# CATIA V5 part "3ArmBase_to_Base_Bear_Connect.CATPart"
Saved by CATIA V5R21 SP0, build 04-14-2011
Part number: ArmBase_to_Base_Bear_Connect
Bounding box of the stored display mesh (mm): x 0 to 8, y -32 to 32, z -25.5 to 25.5
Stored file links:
  K:\Arm_Detailed_Design_Assembly_Manu\3ArmBase_to_Base_Bear_Connect.CATPart
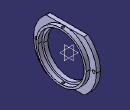
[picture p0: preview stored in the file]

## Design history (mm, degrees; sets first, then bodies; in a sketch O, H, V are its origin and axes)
Body1 (main body)
  Sketch1 on yz-plane, origin (0, 0, 0), H (0, 1, 0), V (0, 0, 1)
    circle A1 centre (0, 0) radius 32
    circle A2 centre (0, 0) radius 21.5
    radius A2 = 21.5
    radius A1 = 32
  Pad1: profile Sketch1, direction (1, 0, 0), length 4
  Sketch2 on end face of Pad1, origin (4, 0, 0), H (0, 1, 0), V (0, 0, 1)
    circle A1 centre (0, 0) radius 23.5
    circle A2 centre (0, 0) radius 25.5
    radius A2 = 25.5
    radius A1 = 23.5
  Pad2: profile Sketch2, direction (1, 0, 0), length 4
  Sketch3 on start face of Pad1, origin (0, 0, 0), H (0, -1, 0), V (0, 0, 1)
    circle A1 centre (29, 0) radius 1.5
    point P1 (29, 0)
    point P2 (30.5, 0)
    circle A2 centre (-29, 0) radius 1.5
    point P3 (-29, 0)
    line L1 (-30.0408, 34.0267) -> (31.4698, 34.0267)
    line L2 (31.4698, 34.0267) -> (31.4698, 25.5)
    line L3 (31.4698, 25.5) -> (-30.0408, 25.5)
    line L4 (-30.0408, 25.5) -> (-30.0408, 34.0267)
    reference projected circle E1 centre (0, 0) radius 25.5 from edge [end face of Pad1 | face of Pad2 from Sketch2.A2]
    line L5 (26.753, -25.5) -> (-25.9884, -25.5)
    line L6 (-25.9884, -25.5) -> (-25.9884, -39.4596)
    line L7 (-25.9884, -39.4596) -> (26.753, -39.4596)
    line L8 (26.753, -39.4596) -> (26.753, -25.5)
    reference projected circle E2 centre (0, 0) radius 25.5 from edge [end face of Pad1 | face of Pad2 from Sketch2.A2]
    radius A1 = 1.5
    radius A2 = 1.5
    distance V P1 = 29
    distance V P3 = 29
    coincidence: P1 H, A1 P2, P2 H, P3 H
    horizontal: L1 H, L3 H, L5 H, L7 H
    vertical: L2 V, L4 V, L6 V, L8 V
    tangency: E1 L3, L5 E2
  Pocket1: profile Sketch3, direction (1, 0, 0), through (limit type 3)
  Sketch4 on xy-plane, origin (0, 0, 0), H (1, 0, 0), V (0, 1, 0)
    circle A1 centre (6, 0) radius 1.25
    point P1 (6, 0)
    reference projected line E1 (8, 25.5) -> (8, -25.5) from edge [face of Pad2 from Sketch2.A2 | end face of Pad2]
    radius A1 = 1.25
    distance P1 E1 = 2
    coincidence: P1 H
  Pocket2: profile Sketch4, direction (0, 0, -1), length 40, mirrored extent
